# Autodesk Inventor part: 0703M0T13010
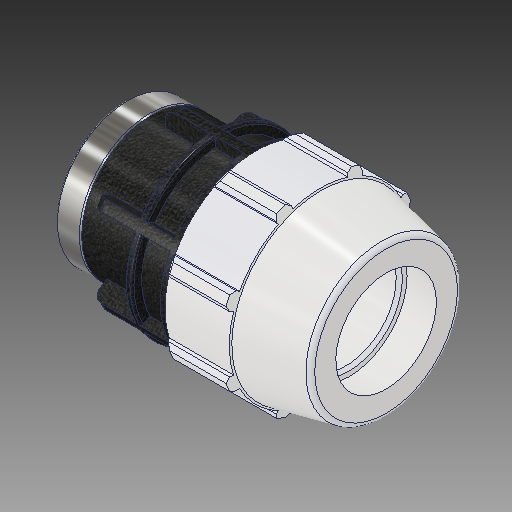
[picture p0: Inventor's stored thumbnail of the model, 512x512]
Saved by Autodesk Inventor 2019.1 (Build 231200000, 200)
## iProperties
Created: 2017-02
Part Number: 0703M0T13010
Material: PVC-Piping
Description: PLASSON FEMALE ADAPTOR G 1 1/4'' - 1''F
Document SubType Name: Modeling
Designer: KIM
Mass: 92.6774 g
Surface Area: 199.44 cm^2
Volume: 66.1981 cm^3
Density: 1.4 g/cm^3
Appearance: PTFE
Author: KIM
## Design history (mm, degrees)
derived "0703M0T.ipt"
feature "Solid1::0703M0T.ipt"
tag "TaggingFeature1"
body "Solid1"
other parameters: "d2" = 42.1, "d4" = 15.56657, "d5" = 27.2415, "d7" = 82.042, "d9" = 15.56657, "d11" = 3.11331, "d12" = 65.6336, "d13" = 120 deg, "d14" = 63.15, "d15" = 12 deg, "d16" = 73.8378, "d18" = 2.105, "d19" = 35 deg, "d20" = 17.5 deg, "d21" = 76.29906, "d23" = 0, "d25" = 360 deg, "d27" = 1.64084, "d34" = 4.1021, "d35" = 32.6898, "d36" = 0, "d42" = 27.2415, "d43" = 2.46126, "d46" = 1.263, "d49" = 83.058, "d51" = 108.966, "d53" = 0.842, "d55" = 360 deg, "d61" = 21.082, "d62" = 39.995, "d63" = 30.291, "d64" = 36.322, "d65" = 4.1021, "d66" = 0.5, "d67" = 1, "d68" = 10.541, "d69" = 59.07024, "d70" = 1.27, "d_" = 42.1, "E_" = 82.042, "H_" = 108.966, "l_" = 83.058, "l_2" = 21.082, "G_" = 30.291
